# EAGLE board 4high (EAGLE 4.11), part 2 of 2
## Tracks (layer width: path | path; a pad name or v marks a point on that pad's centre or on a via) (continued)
N$723 (continued)
  Bottom 0.381: IC53.35 IC54.35 IC55.35 IC56.35
N$724
  Bottom 0.381: IC53.36 IC54.36 IC55.36 IC56.36
N$725
  Bottom 0.381: IC53.37 IC54.37 IC55.37 IC56.37
N$726
  Bottom 0.381: IC53.38 IC54.38 IC55.38 IC56.38
N$727
  Bottom 0.381: IC53.39 IC54.39 IC55.39 IC56.39
N$728
  Bottom 0.381: IC53.40 IC54.40 IC55.40 IC56.40
N$729
  Bottom 0.381: IC53.41 IC54.41 IC55.41 IC56.41
N$730
  Bottom 0.381: IC53.42 IC54.42 IC55.42 IC56.42
N$731
  Bottom 0.381: IC57.1 IC60.1 IC58.1 IC59.1
N$732
  Bottom 0.381: IC57.2 IC60.2 IC58.2 IC59.2
N$733
  Bottom 0.381: IC57.3 IC60.3 IC58.3 IC59.3
N$734
  Bottom 0.381: IC57.4 IC60.4 IC58.4 IC59.4
N$735
  Bottom 0.381: IC57.5 IC60.5 IC58.5 IC59.5
N$736
  Bottom 0.381: IC57.6 IC60.6 IC58.6 IC59.6
N$737
  Bottom 0.381: IC57.7 IC60.7 IC58.7 IC59.7
N$738
  Bottom 0.381: IC57.8 IC60.8 IC58.8 IC59.8
N$739
  Bottom 0.381: IC57.9 IC60.9 IC58.9 IC59.9
N$740
  Bottom 0.381: IC57.10 IC60.10 IC58.10 IC59.10
N$741
  Bottom 0.381: IC57.11 IC60.11 IC58.11 IC59.11
N$742
  Bottom 0.381: IC57.12 IC60.12 IC58.12 IC59.12
N$743
  Bottom 0.381: IC57.13 IC60.13 IC58.13 IC59.13
N$744
  Bottom 0.381: IC57.14 IC60.14 IC58.14 IC59.14
N$745
  Bottom 0.381: IC57.15 IC60.15 IC58.15 IC59.15
N$746
  Bottom 0.381: IC57.16 IC60.16 IC58.16 IC59.16
N$747
  Bottom 0.381: IC57.17 IC60.17 IC58.17 IC59.17
N$748
  Bottom 0.381: IC57.18 IC60.18 IC58.18 IC59.18
N$749
  Bottom 0.381: IC57.19 IC60.19 IC58.19 IC59.19
N$750
  Bottom 0.381: IC57.20 IC60.20 IC58.20 IC59.20
N$751
  Bottom 0.381: IC57.21 IC60.21 IC58.21 IC59.21
N$752
  Bottom 0.381: IC57.22 IC60.22 IC58.22 IC59.22
N$753
  Bottom 0.381: IC57.23 IC60.23 IC58.23 IC59.23
N$754
  Bottom 0.381: IC57.24 IC60.24 IC58.24 IC59.24
N$755
  Bottom 0.381: IC57.25 IC60.25 IC58.25 IC59.25
N$756
  Bottom 0.381: IC57.26 IC60.26 IC58.26 IC59.26
N$757
  Bottom 0.381: IC57.27 IC60.27 IC58.27 IC59.27
N$758
  Bottom 0.381: IC57.28 IC60.28 IC58.28 IC59.28
N$759
  Bottom 0.381: IC57.29 IC60.29 IC58.29 IC59.29
N$760
  Bottom 0.381: IC57.30 IC60.30 IC58.30 IC59.30
N$761
  Bottom 0.381: IC57.31 IC60.31 IC58.31 IC59.31
N$762
  Bottom 0.381: IC57.32 IC60.32 IC58.32 IC59.32
N$763
  Bottom 0.381: IC57.33 IC60.33 IC58.33 IC59.33
N$764
  Bottom 0.381: IC57.34 IC60.34 IC58.34 IC59.34
N$765
  Bottom 0.381: IC57.35 IC60.35 IC58.35 IC59.35
N$766
  Bottom 0.381: IC57.36 IC60.36 IC58.36 IC59.36
N$767
  Bottom 0.381: IC57.37 IC60.37 IC58.37 IC59.37
N$768
  Bottom 0.381: IC57.38 IC60.38 IC58.38 IC59.38
N$769
  Bottom 0.381: IC57.39 IC60.39 IC58.39 IC59.39
N$770
  Bottom 0.381: IC57.40 IC60.40 IC58.40 IC59.40
N$771
  Bottom 0.381: IC57.41 IC60.41 IC58.41 IC59.41
N$772
  Bottom 0.381: IC57.42 IC60.42 IC58.42 IC59.42
N$773
  Bottom 0.381: IC64.1 IC61.1 IC62.1 IC63.1
N$774
  Bottom 0.381: IC64.2 IC61.2 IC62.2 IC63.2
N$775
  Bottom 0.381: IC64.3 IC61.3 IC62.3 IC63.3
N$776
  Bottom 0.381: IC64.4 IC61.4 IC62.4 IC63.4
N$777
  Bottom 0.381: IC64.5 IC61.5 IC62.5 IC63.5
N$778
  Bottom 0.381: IC64.6 IC61.6 IC62.6 IC63.6
N$779
  Bottom 0.381: IC64.7 IC61.7 IC62.7 IC63.7
N$780
  Bottom 0.381: IC64.8 IC61.8 IC62.8 IC63.8
N$781
  Bottom 0.381: IC64.9 IC61.9 IC62.9 IC63.9
N$782
  Bottom 0.381: IC64.10 IC61.10 IC62.10 IC63.10
N$783
  Bottom 0.381: IC64.11 IC61.11 IC62.11 IC63.11
N$784
  Bottom 0.381: IC64.12 IC61.12 IC62.12 IC63.12
N$785
  Bottom 0.381: IC64.13 IC61.13 IC62.13 IC63.13
N$786
  Bottom 0.381: IC64.14 IC61.14 IC62.14 IC63.14
N$787
  Bottom 0.381: IC64.15 IC61.15 IC62.15 IC63.15
N$788
  Bottom 0.381: IC64.16 IC61.16 IC62.16 IC63.16
N$789
  Bottom 0.381: IC64.17 IC61.17 IC62.17 IC63.17
N$790
  Bottom 0.381: IC64.18 IC61.18 IC62.18 IC63.18
N$791
  Bottom 0.381: IC64.19 IC61.19 IC62.19 IC63.19
N$792
  Bottom 0.381: IC64.20 IC61.20 IC62.20 IC63.20
N$793
  Bottom 0.381: IC64.21 IC61.21 IC62.21 IC63.21
N$794
  Bottom 0.381: IC64.22 IC61.22 IC62.22 IC63.22
N$795
  Bottom 0.381: IC64.23 IC61.23 IC62.23 IC63.23
N$796
  Bottom 0.381: IC64.24 IC61.24 IC62.24 IC63.24
N$797
  Bottom 0.381: IC64.25 IC61.25 IC62.25 IC63.25
N$798
  Bottom 0.381: IC64.26 IC61.26 IC62.26 IC63.26
N$799
  Bottom 0.381: IC64.27 IC61.27 IC62.27 IC63.27
N$800
  Bottom 0.381: IC64.28 IC61.28 IC62.28 IC63.28
N$801
  Bottom 0.381: IC64.29 IC61.29 IC62.29 IC63.29
N$802
  Bottom 0.381: IC64.30 IC61.30 IC62.30 IC63.30
N$803
  Bottom 0.381: IC64.31 IC61.31 IC62.31 IC63.31
N$804
  Bottom 0.381: IC64.32 IC61.32 IC62.32 IC63.32
N$805
  Bottom 0.381: IC64.33 IC61.33 IC62.33 IC63.33
N$806
  Bottom 0.381: IC64.34 IC61.34 IC62.34 IC63.34
N$807
  Bottom 0.381: IC64.35 IC61.35 IC62.35 IC63.35
N$808
  Bottom 0.381: IC64.36 IC61.36 IC62.36 IC63.36
N$809
  Bottom 0.381: IC64.37 IC61.37 IC62.37 IC63.37
N$810
  Bottom 0.381: IC64.38 IC61.38 IC62.38 IC63.38
N$811
  Bottom 0.381: IC64.39 IC61.39 IC62.39 IC63.39
N$812
  Bottom 0.381: IC64.40 IC61.40 IC62.40 IC63.40
N$813
  Bottom 0.381: IC64.41 IC61.41 IC62.41 IC63.41
N$814
  Bottom 0.381: IC64.42 IC61.42 IC62.42 IC63.42
N$815
  Bottom 0.381: IC65.1 IC66.1 IC67.1 IC68.1
N$816
  Bottom 0.381: IC65.2 IC66.2 IC67.2 IC68.2
N$817
  Bottom 0.381: IC65.3 IC66.3 IC67.3 IC68.3
N$818
  Bottom 0.381: IC65.4 IC66.4 IC67.4 IC68.4
N$819
  Bottom 0.381: IC65.5 IC66.5 IC67.5 IC68.5
N$820
  Bottom 0.381: IC65.6 IC66.6 IC67.6 IC68.6
N$821
  Bottom 0.381: IC65.7 IC66.7 IC67.7 IC68.7
N$822
  Bottom 0.381: IC65.8 IC66.8 IC67.8 IC68.8
N$823
  Bottom 0.381: IC65.9 IC66.9 IC67.9 IC68.9
N$824
  Bottom 0.381: IC65.10 IC66.10 IC67.10 IC68.10
N$825
  Bottom 0.381: IC65.11 IC66.11 IC67.11 IC68.11
N$826
  Bottom 0.381: IC65.12 IC66.12 IC67.12 IC68.12
N$827
  Bottom 0.381: IC65.13 IC66.13 IC67.13 IC68.13
N$828
  Bottom 0.381: IC65.14 IC66.14 IC67.14 IC68.14
N$829
  Bottom 0.381: IC65.15 IC66.15 IC67.15 IC68.15
N$830
  Bottom 0.381: IC65.16 IC66.16 IC67.16 IC68.16
N$831
  Bottom 0.381: IC65.17 IC66.17 IC67.17 IC68.17
N$832
  Bottom 0.381: IC65.18 IC66.18 IC67.18 IC68.18
N$833
  Bottom 0.381: IC65.19 IC66.19 IC67.19 IC68.19
N$834
  Bottom 0.381: IC65.20 IC66.20 IC67.20 IC68.20
N$835
  Bottom 0.381: IC65.21 IC66.21 IC67.21 IC68.21
N$836
  Bottom 0.381: IC65.22 IC66.22 IC67.22 IC68.22
N$837
  Bottom 0.381: IC65.23 IC66.23 IC67.23 IC68.23
N$838
  Bottom 0.381: IC65.24 IC66.24 IC67.24 IC68.24
N$839
  Bottom 0.381: IC65.25 IC66.25 IC67.25 IC68.25
N$840
  Bottom 0.381: IC65.26 IC66.26 IC67.26 IC68.26
N$841
  Bottom 0.381: IC65.27 IC66.27 IC67.27 IC68.27
N$842
  Bottom 0.381: IC65.28 IC66.28 IC67.28 IC68.28
N$843
  Bottom 0.381: IC65.29 IC66.29 IC67.29 IC68.29
N$844
  Bottom 0.381: IC65.30 IC66.30 IC67.30 IC68.30
N$845
  Bottom 0.381: IC65.31 IC66.31 IC67.31 IC68.31
N$846
  Bottom 0.381: IC65.32 IC66.32 IC67.32 IC68.32
N$847
  Bottom 0.381: IC65.33 IC66.33 IC67.33 IC68.33
N$848
  Bottom 0.381: IC65.34 IC66.34 IC67.34 IC68.34
N$849
  Bottom 0.381: IC65.35 IC66.35 IC67.35 IC68.35
N$850
  Bottom 0.381: IC65.36 IC66.36 IC67.36 IC68.36
N$851
  Bottom 0.381: IC65.37 IC66.37 IC67.37 IC68.37
N$852
  Bottom 0.381: IC65.38 IC66.38 IC67.38 IC68.38
N$853
  Bottom 0.381: IC65.39 IC66.39 IC67.39 IC68.39
N$854
  Bottom 0.381: IC65.40 IC66.40 IC67.40 IC68.40
N$855
  Bottom 0.381: IC65.41 IC66.41 IC67.41 IC68.41
N$856
  Bottom 0.381: IC65.42 IC66.42 IC67.42 IC68.42
N$857
  Bottom 0.381: IC69.1 IC70.1 IC71.1 IC72.1
N$858
  Bottom 0.381: IC69.2 IC70.2 IC71.2 IC72.2
N$859
  Bottom 0.381: IC69.3 IC70.3 IC71.3 IC72.3
N$860
  Bottom 0.381: IC69.4 IC70.4 IC71.4 IC72.4
N$861
  Bottom 0.381: IC69.5 IC70.5 IC71.5 IC72.5
N$862
  Bottom 0.381: IC69.6 IC70.6 IC71.6 IC72.6
N$863
  Bottom 0.381: IC69.7 IC70.7 IC71.7 IC72.7
N$864
  Bottom 0.381: IC69.8 IC70.8 IC71.8 IC72.8
N$865
  Bottom 0.381: IC69.9 IC70.9 IC71.9 IC72.9
N$866
  Bottom 0.381: IC69.10 IC70.10 IC71.10 IC72.10
N$867
  Bottom 0.381: IC69.11 IC70.11 IC71.11 IC72.11
N$868
  Bottom 0.381: IC69.12 IC70.12 IC71.12 IC72.12
N$869
  Bottom 0.381: IC69.13 IC70.13 IC71.13 IC72.13
N$870
  Bottom 0.381: IC69.14 IC70.14 IC71.14 IC72.14
N$871
  Bottom 0.381: IC69.15 IC70.15 IC71.15 IC72.15
N$872
  Bottom 0.381: IC69.16 IC70.16 IC71.16 IC72.16
N$873
  Bottom 0.381: IC69.17 IC70.17 IC71.17 IC72.17
N$874
  Bottom 0.381: IC69.18 IC70.18 IC71.18 IC72.18
N$875
  Bottom 0.381: IC69.19 IC70.19 IC71.19 IC72.19
N$876
  Bottom 0.381: IC69.20 IC70.20 IC71.20 IC72.20
N$877
  Bottom 0.381: IC69.21 IC70.21 IC71.21 IC72.21
N$878
  Bottom 0.381: IC69.22 IC70.22 IC71.22 IC72.22
N$879
  Bottom 0.381: IC69.23 IC70.23 IC71.23 IC72.23
N$880
  Bottom 0.381: IC69.24 IC70.24 IC71.24 IC72.24
N$881
  Bottom 0.381: IC69.25 IC70.25 IC71.25 IC72.25
N$882
  Bottom 0.381: IC69.26 IC70.26 IC71.26 IC72.26
N$883
  Bottom 0.381: IC69.27 IC70.27 IC71.27 IC72.27
N$884
  Bottom 0.381: IC69.28 IC70.28 IC71.28 IC72.28
N$885
  Bottom 0.381: IC69.29 IC70.29 IC71.29 IC72.29
N$886
  Bottom 0.381: IC69.30 IC70.30 IC71.30 IC72.30
N$887
  Bottom 0.381: IC69.31 IC70.31 IC71.31 IC72.31
N$888
  Bottom 0.381: IC69.32 IC70.32 IC71.32 IC72.32
N$889
  Bottom 0.381: IC69.33 IC70.33 IC71.33 IC72.33
N$890
  Bottom 0.381: IC69.34 IC70.34 IC71.34 IC72.34
N$891
  Bottom 0.381: IC69.35 IC70.35 IC71.35 IC72.35
N$892
  Bottom 0.381: IC69.36 IC70.36 IC71.36 IC72.36
N$893
  Bottom 0.381: IC69.37 IC70.37 IC71.37 IC72.37
N$894
  Bottom 0.381: IC69.38 IC70.38 IC71.38 IC72.38
N$895
  Bottom 0.381: IC69.39 IC70.39 IC71.39 IC72.39
N$896
  Bottom 0.381: IC69.40 IC70.40 IC71.40 IC72.40
N$897
  Bottom 0.381: IC69.41 IC70.41 IC71.41 IC72.41
N$898
  Bottom 0.381: IC69.42 IC70.42 IC71.42 IC72.42
N$899
  Bottom 0.381: IC74.1 IC75.1 IC76.1 IC73.1
N$900
  Bottom 0.381: IC74.2 IC75.2 IC76.2 IC73.2
N$901
  Bottom 0.381: IC74.3 IC75.3 IC76.3 IC73.3
N$902
  Bottom 0.381: IC74.4 IC75.4 IC76.4 IC73.4
N$903
  Bottom 0.381: IC74.5 IC75.5 IC76.5 IC73.5
N$904
  Bottom 0.381: IC74.6 IC75.6 IC76.6 IC73.6
N$905
  Bottom 0.381: IC74.7 IC75.7 IC76.7 IC73.7
N$906
  Bottom 0.381: IC74.8 IC75.8 IC76.8 IC73.8
N$907
  Bottom 0.381: IC74.9 IC75.9 IC76.9 IC73.9
N$908
  Bottom 0.381: IC74.10 IC75.10 IC76.10 IC73.10
N$909
  Bottom 0.381: IC74.11 IC75.11 IC76.11 IC73.11
N$910
  Bottom 0.381: IC74.12 IC75.12 IC76.12 IC73.12
N$911
  Bottom 0.381: IC74.13 IC75.13 IC76.13 IC73.13
N$912
  Bottom 0.381: IC74.14 IC75.14 IC76.14 IC73.14
N$913
  Bottom 0.381: IC74.15 IC75.15 IC76.15 IC73.15
N$914
  Bottom 0.381: IC74.16 IC75.16 IC76.16 IC73.16
N$915
  Bottom 0.381: IC74.17 IC75.17 IC76.17 IC73.17
N$916
  Bottom 0.381: IC74.18 IC75.18 IC76.18 IC73.18
N$917
  Bottom 0.381: IC74.19 IC75.19 IC76.19 IC73.19
N$918
  Bottom 0.381: IC74.20 IC75.20 IC76.20 IC73.20
N$919
  Bottom 0.381: IC74.21 IC75.21 IC76.21 IC73.21
N$920
  Bottom 0.381: IC74.22 IC75.22 IC76.22 IC73.22
N$921
  Bottom 0.381: IC74.23 IC75.23 IC76.23 IC73.23
N$922
  Bottom 0.381: IC74.24 IC75.24 IC76.24 IC73.24
N$923
  Bottom 0.381: IC74.25 IC75.25 IC76.25 IC73.25
N$924
  Bottom 0.381: IC74.26 IC75.26 IC76.26 IC73.26
N$925
  Bottom 0.381: IC74.27 IC75.27 IC76.27 IC73.27
N$926
  Bottom 0.381: IC74.28 IC75.28 IC76.28 IC73.28
N$927
  Bottom 0.381: IC74.29 IC75.29 IC76.29 IC73.29
N$928
  Bottom 0.381: IC74.30 IC75.30 IC76.30 IC73.30
N$929
  Bottom 0.381: IC74.31 IC75.31 IC76.31 IC73.31
N$930
  Bottom 0.381: IC74.32 IC75.32 IC76.32 IC73.32
N$931
  Bottom 0.381: IC74.33 IC75.33 IC76.33 IC73.33
N$932
  Bottom 0.381: IC74.34 IC75.34 IC76.34 IC73.34
N$933
  Bottom 0.381: IC74.35 IC75.35 IC76.35 IC73.35
N$934
  Bottom 0.381: IC74.36 IC75.36 IC76.36 IC73.36
N$935
  Bottom 0.381: IC74.37 IC75.37 IC76.37 IC73.37
N$936
  Bottom 0.381: IC74.38 IC75.38 IC76.38 IC73.38
N$937
  Bottom 0.381: IC74.39 IC75.39 IC76.39 IC73.39
N$938
  Bottom 0.381: IC74.40 IC75.40 IC76.40 IC73.40
N$939
  Bottom 0.381: IC74.41 IC75.41 IC76.41 IC73.41
N$940
  Bottom 0.381: IC74.42 IC75.42 IC76.42 IC73.42
N$941
  Bottom 0.381: IC79.1 IC80.1 IC77.1 IC78.1
N$942
  Bottom 0.381: IC79.2 IC80.2 IC77.2 IC78.2
N$943
  Bottom 0.381: IC79.3 IC80.3 IC77.3 IC78.3
N$944
  Bottom 0.381: IC79.4 IC80.4 IC77.4 IC78.4
N$945
  Bottom 0.381: IC79.5 IC80.5 IC77.5 IC78.5
N$946
  Bottom 0.381: IC79.6 IC80.6 IC77.6 IC78.6
N$947
  Bottom 0.381: IC79.7 IC80.7 IC77.7 IC78.7
N$948
  Bottom 0.381: IC79.8 IC80.8 IC77.8 IC78.8
N$949
  Bottom 0.381: IC79.9 IC80.9 IC77.9 IC78.9
N$950
  Bottom 0.381: IC79.10 IC80.10 IC77.10 IC78.10
N$951
  Bottom 0.381: IC79.11 IC80.11 IC77.11 IC78.11
N$952
  Bottom 0.381: IC79.12 IC80.12 IC77.12 IC78.12
N$953
  Bottom 0.381: IC79.13 IC80.13 IC77.13 IC78.13
N$954
  Bottom 0.381: IC79.14 IC80.14 IC77.14 IC78.14
N$955
  Bottom 0.381: IC79.15 IC80.15 IC77.15 IC78.15
N$956
  Bottom 0.381: IC79.16 IC80.16 IC77.16 IC78.16
N$957
  Bottom 0.381: IC79.17 IC80.17 IC77.17 IC78.17
N$958
  Bottom 0.381: IC79.18 IC80.18 IC77.18 IC78.18
N$959
  Bottom 0.381: IC79.19 IC80.19 IC77.19 IC78.19
N$960
  Bottom 0.381: IC79.20 IC80.20 IC77.20 IC78.20
N$961
  Bottom 0.381: IC79.21 IC80.21 IC77.21 IC78.21
N$962
  Bottom 0.381: IC79.22 IC80.22 IC77.22 IC78.22
N$963
  Bottom 0.381: IC79.23 IC80.23 IC77.23 IC78.23
N$964
  Bottom 0.381: IC79.24 IC80.24 IC77.24 IC78.24
N$965
  Bottom 0.381: IC79.25 IC80.25 IC77.25 IC78.25
N$966
  Bottom 0.381: IC79.26 IC80.26 IC77.26 IC78.26
N$967
  Bottom 0.381: IC79.27 IC80.27 IC77.27 IC78.27
N$968
  Bottom 0.381: IC79.28 IC80.28 IC77.28 IC78.28
N$969
  Bottom 0.381: IC79.29 IC80.29 IC77.29 IC78.29
N$970
  Bottom 0.381: IC79.30 IC80.30 IC77.30 IC78.30
N$971
  Bottom 0.381: IC79.31 IC80.31 IC77.31 IC78.31
N$972
  Bottom 0.381: IC79.32 IC80.32 IC77.32 IC78.32
N$973
  Bottom 0.381: IC79.33 IC80.33 IC77.33 IC78.33
N$974
  Bottom 0.381: IC79.34 IC80.34 IC77.34 IC78.34
N$975
  Bottom 0.381: IC79.35 IC80.35 IC77.35 IC78.35
N$976
  Bottom 0.381: IC79.36 IC80.36 IC77.36 IC78.36
N$977
  Bottom 0.381: IC79.37 IC80.37 IC77.37 IC78.37
N$978
  Bottom 0.381: IC79.38 IC80.38 IC77.38 IC78.38
N$979
  Bottom 0.381: IC79.39 IC80.39 IC77.39 IC78.39
N$980
  Bottom 0.381: IC79.40 IC80.40 IC77.40 IC78.40
N$981
  Bottom 0.381: IC79.41 IC80.41 IC77.41 IC78.41
N$982
  Bottom 0.381: IC79.42 IC80.42 IC77.42 IC78.42
N$983
  Bottom 0.381: IC84.1 IC81.1 IC82.1 IC83.1
N$984
  Bottom 0.381: IC84.2 IC81.2 IC82.2 IC83.2
N$985
  Bottom 0.381: IC84.3 IC81.3 IC82.3 IC83.3
N$986
  Bottom 0.381: IC84.4 IC81.4 IC82.4 IC83.4
N$987
  Bottom 0.381: IC84.5 IC81.5 IC82.5 IC83.5
N$988
  Bottom 0.381: IC84.6 IC81.6 IC82.6 IC83.6
N$989
  Bottom 0.381: IC84.7 IC81.7 IC82.7 IC83.7
N$990
  Bottom 0.381: IC84.8 IC81.8 IC82.8 IC83.8
N$991
  Bottom 0.381: IC84.9 IC81.9 IC82.9 IC83.9
N$992
  Bottom 0.381: IC84.10 IC81.10 IC82.10 IC83.10
N$993
  Bottom 0.381: IC84.11 IC81.11 IC82.11 IC83.11
N$994
  Bottom 0.381: IC84.12 IC81.12 IC82.12 IC83.12
N$995
  Bottom 0.381: IC84.13 IC81.13 IC82.13 IC83.13
N$996
  Bottom 0.381: IC84.14 IC81.14 IC82.14 IC83.14
N$997
  Bottom 0.381: IC84.15 IC81.15 IC82.15 IC83.15
N$998
  Bottom 0.381: IC84.16 IC81.16 IC82.16 IC83.16
N$999
  Bottom 0.381: IC84.17 IC81.17 IC82.17 IC83.17
N$1000
  Bottom 0.381: IC84.18 IC81.18 IC82.18 IC83.18
N$1001
  Bottom 0.381: IC84.19 IC81.19 IC82.19 IC83.19
N$1002
  Bottom 0.381: IC84.20 IC81.20 IC82.20 IC83.20
N$1003
  Bottom 0.381: IC84.21 IC81.21 IC82.21 IC83.21
N$1004
  Bottom 0.381: IC84.22 IC81.22 IC82.22 IC83.22
N$1005
  Bottom 0.381: IC84.23 IC81.23 IC82.23 IC83.23
N$1006
  Bottom 0.381: IC84.24 IC81.24 IC82.24 IC83.24
N$1007
  Bottom 0.381: IC84.25 IC81.25 IC82.25 IC83.25
N$1008
  Bottom 0.381: IC84.26 IC81.26 IC82.26 IC83.26
N$1009
  Bottom 0.381: IC84.27 IC81.27 IC82.27 IC83.27
N$1010
  Bottom 0.381: IC84.28 IC81.28 IC82.28 IC83.28
N$1011
  Bottom 0.381: IC84.29 IC81.29 IC82.29 IC83.29
N$1012
  Bottom 0.381: IC84.30 IC81.30 IC82.30 IC83.30
N$1013
  Bottom 0.381: IC84.31 IC81.31 IC82.31 IC83.31
N$1014
  Bottom 0.381: IC84.32 IC81.32 IC82.32 IC83.32
N$1015
  Bottom 0.381: IC84.33 IC81.33 IC82.33 IC83.33
N$1016
  Bottom 0.381: IC84.34 IC81.34 IC82.34 IC83.34
N$1017
  Bottom 0.381: IC84.35 IC81.35 IC82.35 IC83.35
N$1018
  Bottom 0.381: IC84.36 IC81.36 IC82.36 IC83.36
N$1019
  Bottom 0.381: IC84.37 IC81.37 IC82.37 IC83.37
N$1020
  Bottom 0.381: IC84.38 IC81.38 IC82.38 IC83.38
N$1021
  Bottom 0.381: IC84.39 IC81.39 IC82.39 IC83.39
N$1022
  Bottom 0.381: IC84.40 IC81.40 IC82.40 IC83.40
N$1023
  Bottom 0.381: IC84.41 IC81.41 IC82.41 IC83.41
N$1024
  Bottom 0.381: IC84.42 IC81.42 IC82.42 IC83.42
N$1025
  Bottom 0.381: IC88.1 IC87.1 IC86.1 IC85.1
N$1026
  Bottom 0.381: IC88.2 IC87.2 IC86.2 IC85.2
N$1027
  Bottom 0.381: IC88.3 IC87.3 IC86.3 IC85.3
N$1028
  Bottom 0.381: IC88.4 IC87.4 IC86.4 IC85.4
N$1029
  Bottom 0.381: IC88.5 IC87.5 IC86.5 IC85.5
N$1030
  Bottom 0.381: IC88.6 IC87.6 IC86.6 IC85.6
N$1031
  Bottom 0.381: IC88.7 IC87.7 IC86.7 IC85.7
N$1032
  Bottom 0.381: IC88.8 IC87.8 IC86.8 IC85.8
N$1033
  Bottom 0.381: IC88.9 IC87.9 IC86.9 IC85.9
N$1034
  Bottom 0.381: IC88.10 IC87.10 IC86.10 IC85.10
N$1035
  Bottom 0.381: IC88.11 IC87.11 IC86.11 IC85.11
N$1036
  Bottom 0.381: IC88.12 IC87.12 IC86.12 IC85.12
N$1037
  Bottom 0.381: IC88.13 IC87.13 IC86.13 IC85.13
N$1038
  Bottom 0.381: IC88.14 IC87.14 IC86.14 IC85.14
N$1039
  Bottom 0.381: IC88.15 IC87.15 IC86.15 IC85.15
N$1040
  Bottom 0.381: IC88.16 IC87.16 IC86.16 IC85.16
N$1041
  Bottom 0.381: IC88.17 IC87.17 IC86.17 IC85.17
N$1042
  Bottom 0.381: IC88.18 IC87.18 IC86.18 IC85.18
N$1043
  Bottom 0.381: IC88.19 IC87.19 IC86.19 IC85.19
N$1044
  Bottom 0.381: IC88.20 IC87.20 IC86.20 IC85.20
N$1045
  Bottom 0.381: IC88.21 IC87.21 IC86.21 IC85.21
N$1046
  Bottom 0.381: IC88.22 IC87.22 IC86.22 IC85.22
N$1047
  Bottom 0.381: IC88.23 IC87.23 IC86.23 IC85.23
N$1048
  Bottom 0.381: IC88.24 IC87.24 IC86.24 IC85.24
N$1049
  Bottom 0.381: IC88.25 IC87.25 IC86.25 IC85.25
N$1050
  Bottom 0.381: IC88.26 IC87.26 IC86.26 IC85.26
N$1051
  Bottom 0.381: IC88.27 IC87.27 IC86.27 IC85.27
N$1052
  Bottom 0.381: IC88.28 IC87.28 IC86.28 IC85.28
N$1053
  Bottom 0.381: IC88.29 IC87.29 IC86.29 IC85.29
N$1054
  Bottom 0.381: IC88.30 IC87.30 IC86.30 IC85.30
N$1055
  Bottom 0.381: IC88.31 IC87.31 IC86.31 IC85.31
N$1056
  Bottom 0.381: IC88.32 IC87.32 IC86.32 IC85.32
N$1057
  Bottom 0.381: IC88.33 IC87.33 IC86.33 IC85.33
N$1058
  Bottom 0.381: IC88.34 IC87.34 IC86.34 IC85.34
N$1059
  Bottom 0.381: IC88.35 IC87.35 IC86.35 IC85.35
N$1060
  Bottom 0.381: IC88.36 IC87.36 IC86.36 IC85.36
N$1061
  Bottom 0.381: IC88.37 IC87.37 IC86.37 IC85.37
N$1062
  Bottom 0.381: IC88.38 IC87.38 IC86.38 IC85.38
N$1063
  Bottom 0.381: IC88.39 IC87.39 IC86.39 IC85.39
N$1064
  Bottom 0.381: IC88.40 IC87.40 IC86.40 IC85.40
N$1065
  Bottom 0.381: IC88.41 IC87.41 IC86.41 IC85.41
N$1066
  Bottom 0.381: IC88.42 IC87.42 IC86.42 IC85.42
N$1067
  Bottom 0.381: IC92.1 IC91.1 IC90.1 IC89.1
N$1068
  Bottom 0.381: IC92.2 IC91.2 IC90.2 IC89.2
N$1069
  Bottom 0.381: IC92.3 IC91.3 IC90.3 IC89.3
N$1070
  Bottom 0.381: IC92.4 IC91.4 IC90.4 IC89.4
N$1071
  Bottom 0.381: IC92.5 IC91.5 IC90.5 IC89.5
N$1072
  Bottom 0.381: IC92.6 IC91.6 IC90.6 IC89.6
N$1073
  Bottom 0.381: IC92.7 IC91.7 IC90.7 IC89.7
N$1074
  Bottom 0.381: IC92.8 IC91.8 IC90.8 IC89.8
N$1075
  Bottom 0.381: IC92.9 IC91.9 IC90.9 IC89.9
N$1076
  Bottom 0.381: IC92.10 IC91.10 IC90.10 IC89.10
N$1077
  Bottom 0.381: IC92.11 IC91.11 IC90.11 IC89.11
N$1078
  Bottom 0.381: IC92.12 IC91.12 IC90.12 IC89.12
N$1079
  Bottom 0.381: IC92.13 IC91.13 IC90.13 IC89.13
N$1080
  Bottom 0.381: IC92.14 IC91.14 IC90.14 IC89.14
N$1081
  Bottom 0.381: IC92.15 IC91.15 IC90.15 IC89.15
N$1082
  Bottom 0.381: IC92.16 IC91.16 IC90.16 IC89.16
N$1083
  Bottom 0.381: IC92.17 IC91.17 IC90.17 IC89.17
N$1084
  Bottom 0.381: IC92.18 IC91.18 IC90.18 IC89.18
N$1085
  Bottom 0.381: IC92.19 IC91.19 IC90.19 IC89.19
N$1086
  Bottom 0.381: IC92.20 IC91.20 IC90.20 IC89.20
N$1087
  Bottom 0.381: IC92.21 IC91.21 IC90.21 IC89.21
N$1088
  Bottom 0.381: IC92.22 IC91.22 IC90.22 IC89.22
N$1089
  Bottom 0.381: IC92.23 IC91.23 IC90.23 IC89.23
N$1090
  Bottom 0.381: IC92.24 IC91.24 IC90.24 IC89.24
N$1091
  Bottom 0.381: IC92.25 IC91.25 IC90.25 IC89.25
N$1092
  Bottom 0.381: IC92.26 IC91.26 IC90.26 IC89.26
N$1093
  Bottom 0.381: IC92.27 IC91.27 IC90.27 IC89.27
N$1094
  Bottom 0.381: IC92.28 IC91.28 IC90.28 IC89.28
N$1095
  Bottom 0.381: IC92.29 IC91.29 IC90.29 IC89.29
N$1096
  Bottom 0.381: IC92.30 IC91.30 IC90.30 IC89.30
N$1097
  Bottom 0.381: IC92.31 IC91.31 IC90.31 IC89.31
N$1098
  Bottom 0.381: IC92.32 IC91.32 IC90.32 IC89.32
N$1151
  Bottom 0.381: SV1.A 15.88,187.96 20.32,192.41 U$2.1
N$1152
  Bottom 0.381: SV1.C 15.88,185.42 17.14,186.69 21.59,186.69 24.13,189.23 U$2.2
N$1153
  Bottom 0.381: SV1.E 15.88,182.88 17.14,184.15 22.23,184.15 24.13,186.06 U$2.3
N$1154
  Bottom 0.381: SV1.H 15.88,180.34 17.14,181.61 22.86,181.61 24.13,182.88 U$2.4
N$1155
  Bottom 0.381: SV1.K 15.88,177.8 17.14,179.07 24.77,179.07 U$2.5
N$1156
  Bottom 0.381: SV1.M 15.88,175.26 17.14,176.53 U$2.6
N$1157
  Bottom 0.381: SV1.P 15.88,172.72 17.14,173.99 24.77,173.99 U$2.7
N$1158
  Bottom 0.381: SV1.S 15.88,170.18 17.14,171.45 22.86,171.45 24.13,170.18 U$2.8
N$1159
  Bottom 0.381: SV1.U 15.88,167.64 17.14,166.37 24.77,166.37 U$2.9
N$1160
  Bottom 0.381: SV1.W 15.88,165.1 17.14,163.83 U$2.10
N$1161
  Bottom 0.381: SV1.Y 15.88,162.56 17.14,161.29 24.77,161.29 U$2.11
N$1162
  Bottom 0.381: SV1.AA 15.88,160.02 17.14,158.75 22.86,158.75 24.13,157.48 U$2.12
N$1163
  Bottom 0.381: SV1.CC 15.88,157.48 17.14,156.21 22.23,156.21 24.13,154.31 U$2.13
N$1164
  Bottom 0.381: SV1.EE 15.88,154.94 17.14,153.67 21.59,153.67 24.13,151.13 U$2.14
N$1165
  Bottom 0.381: SV1.HH 15.88,152.4 17.14,151.13 20.95,151.13 24.13,147.96 U$2.15
N$1166
  Bottom 0.381: SV1.KK 15.88,149.86 17.14,148.59 20.32,148.59 24.13,144.78 U$2.16
N$1167
  Bottom 0.381: SV1.MM 15.88,147.32 17.14,146.05 19.68,146.05 24.13,141.61 U$2.17
N$1168
  Bottom 0.381: SV1.PP 15.88,144.78 17.14,143.51 19.05,143.51 24.13,138.43 U$2.18
N$1169
  Bottom 0.381: SV1.SS 15.88,142.24 17.14,140.97 18.41,140.97 24.13,135.26 U$2.19
N$1170
  Bottom 0.381: SV1.UU 15.88,139.7 23.5,132.08 U$2.20
N$1171
  Bottom 0.381: SV1.B 20.95,187.96 24.13,191.14 27.94,191.14 29.21,192.41 U$4.1
N$1172
  Bottom 0.381: SV1.D 21.59,185.42 24.13,187.96 27.94,187.96 29.21,189.23 U$4.2
N$1173
  Bottom 0.381: SV1.F 22.23,182.88 24.13,184.79 27.94,184.79 29.21,186.06 U$4.3
N$1174
  Bottom 0.381: SV1.J 22.86,180.34 24.13,181.61 27.94,181.61 29.21,182.88 U$4.4
N$1175
  Bottom 0.381: SV1.L 27.3,177.8 29.21,179.71 U$4.5
N$1176
  Bottom 0.381: SV1.N 27.94,175.26 29.21,176.53 U$4.6
N$1177
  Bottom 0.381: SV1.R 22.86,172.72 23.5,172.09 27.94,172.09 29.21,173.36 U$4.7
N$1178
  Top 0.381: SV1.T 22.23,170.18 23.5,171.45 27.94,171.45 29.21,170.18 U$4.8
N$1179
  Bottom 0.381: SV1.V 22.86,167.64 23.5,168.28 27.94,168.28 29.21,167.01 U$4.9
N$1180
  Bottom 0.381: SV1.X 27.94,165.1 29.21,163.83 U$4.10
N$1181
  Bottom 0.381: SV1.Z 27.3,162.56 29.21,160.66 U$4.11
N$1182
  Bottom 0.381: SV1.BB 22.86,160.02 24.13,158.75 27.94,158.75 29.21,157.48 U$4.12
N$1183
  Bottom 0.381: SV1.DD 22.23,157.48 24.13,155.58 27.94,155.58 29.21,154.31 U$4.13
N$1184
  Bottom 0.381: SV1.FF 21.59,154.94 24.13,152.4 27.94,152.4 29.21,151.13 U$4.14
N$1185
  Bottom 0.381: SV1.JJ 20.95,152.4 24.13,149.23 27.94,149.23 29.21,147.96 U$4.15
N$1186
  Bottom 0.381: SV1.LL 20.32,149.86 24.13,146.05 27.94,146.05 29.21,144.78 U$4.16
N$1187
  Bottom 0.381: SV1.NN 19.68,147.32 24.13,142.88 27.94,142.88 29.21,141.61 U$4.17
N$1188
  Bottom 0.381: SV1.RR 19.05,144.78 24.13,139.7 27.94,139.7 29.21,138.43 U$4.18
N$1189
  Bottom 0.381: SV1.TT 18.41,142.24 24.13,136.53 27.94,136.53 29.21,135.26 U$4.19
N$1190
  Bottom 0.381: SV1.VV 17.78,139.07 23.5,133.35 27.94,133.35 29.21,132.08 U$4.20
VCC
  Bottom 0.508: U$1.AA2 260.99,13.97 260.99,21.59 U$5.1 260.99,24.13 255.91,29.21 248.92,29.21 248.92,200.66 247.65,200.66 246.38,201.93 217.17,201.93 215.9,200.66 | 17.78,29.21 17.78,128.27 29.84,128.27 36.2,134.62 36.2,198.76 39.37,201.93 49.53,201.93 50.8,200.66 | 50.8,200.66 50.8,29.21 | 83.82,200.66 83.82,29.21 | 116.84,29.21 116.84,200.66 140.97,200.66 141.6,201.3 141.6,205.74 | 149.86,200.03 149.86,200.66 | 149.86,200.03 149.86,29.21 | 182.88,29.21 182.88,200.66 181.61,200.66 180.34,201.93 | 215.9,200.66 215.9,29.21 | 83.82,200.66 50.8,200.66 | 83.82,200.66 106.68,200.66 111.76,205.74 141.6,205.74 | 141.6,205.74 151.13,205.74 151.76,205.11 151.76,201.93 | 151.76,201.93 149.86,200.03 | 180.34,201.93 151.76,201.93 | 215.9,200.66 214.63,200.66 213.36,201.93 180.34,201.93

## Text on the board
Top: Omnibus Prototype | VRS
Bottom: Omnibus Prototype | VRS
